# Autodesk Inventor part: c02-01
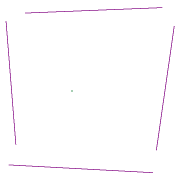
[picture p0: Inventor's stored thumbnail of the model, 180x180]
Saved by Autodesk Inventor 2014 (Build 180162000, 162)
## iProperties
Created: 2013-02
Part Number: c02-01
Material: Generic
Document SubType Name: Modeling
Designer: Thom Tremblay
Density: 1 g/cm^3
Appearance: Default
Author: Thom Tremblay
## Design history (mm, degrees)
sketch "Sketch1"
  geometry: L1 (13.67, -9.538)-(16.571, 10.593); L2 (14.562, 13.56)-(-7.664, 12.676); L3 (-10.73, 11.32)-(-9.138, -8.667); L4 (-10.259, -11.968)-(13.138, -13.231); 1 further point
  constraints: 8 end point, 1 other
